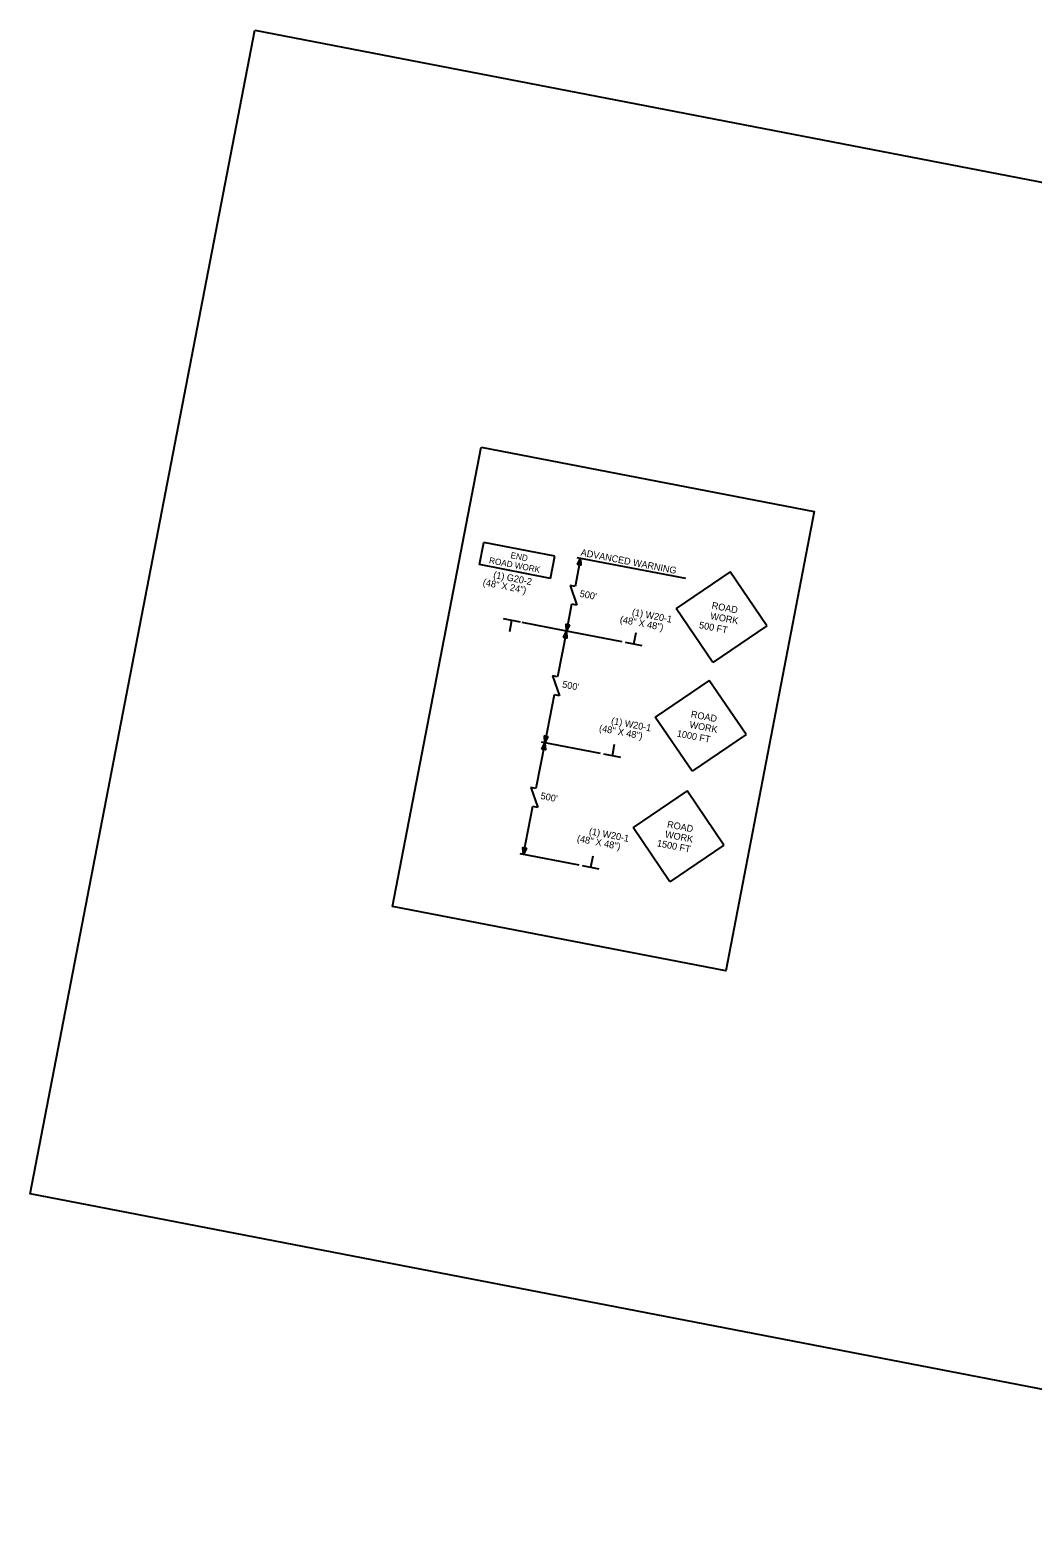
# Model space of a CAD drawing. Extents: x 609776 to 611540, y 418046 to 419372.
# Drawn here: x 609776 to 610658, y 418046 to 419372 of the extents above; entities that cross this region are included whole.
import ezdxf

# ---------------------------------------------------------------- set-up
doc = ezdxf.new("R2010")
doc.units = 0
for name, color, linetype in [('G-Border-Sheet', 7, 'Continuous'), ('R_Draft', 7, 'Continuous'), ('Stage 1B_Sign', 7, 'Continuous')]:
    doc.layers.add(name, color=color, linetype=linetype)

msp = doc.modelspace()

# ---------------------------------------------------------------- linework, layer by layer
at = {"layer": 'G-Border-Sheet'}
msp.add_lwpolyline([(609973.3, 419372.2), (611539.8, 419069.8), (611342.2, 418046.4), (609775.8, 418348.8)], close=True, dxfattribs=at)
at = {"layer": 'R_Draft'}
for p, q in [((610259.9, 418907.8), (610255.1, 418883.1)), ((610352.6, 418889.9), (610257, 418908.3)), ((610255.1, 418883.1), (610250.7, 418884)), ((610250.7, 418884), (610256.8, 418866.5)), ((610252.1, 418867.4), (610247.5, 418843.7)), ((610256.8, 418866.5), (610252.3, 418867.3)), ((610244.6, 418844.2), (610208.5, 418851.2)), ((610247.6, 418843.7), (610239.8, 418803.4)), ((610296.5, 418834.2), (610244.6, 418844.2)), ((610239.8, 418803.4), (610235.3, 418804.3)), ((610235.3, 418804.3), (610241.4, 418786.8)), ((610236.7, 418787.7), (610228.5, 418745.5)), ((610241.4, 418786.8), (610236.9, 418787.7)), ((610228.5, 418745.5), (610220.7, 418705.3)), ((610277.6, 418736), (610225.7, 418746)), ((610220.7, 418705.3), (610216.2, 418706.2)), ((610216.2, 418706.2), (610222.3, 418688.7)), ((610217.6, 418689.6), (610209.5, 418647.4)), ((610222.3, 418688.7), (610217.9, 418689.5)), ((610258.6, 418637.8), (610206.7, 418647.9))]:
    msp.add_line(p, q, dxfattribs=at)
for points in [[(610172.5, 419005.4), (610465.5, 418948.9), (610387.6, 418545), (610094.5, 418601.6)], [(610257.3, 418902.2), (610259.9, 418907.8), (610260.3, 418901.6)], [(610250.2, 418849.3), (610247.6, 418843.7), (610247.2, 418849.8)], [(610245, 418838.1), (610247.6, 418843.7), (610247.9, 418837.5)], [(610226, 418739.9), (610228.6, 418745.5), (610229, 418739.3)], [(610231.2, 418751.1), (610228.6, 418745.5), (610228.3, 418751.7)], [(610212.3, 418652.9), (610209.7, 418647.3), (610209.3, 418653.5)]]:
    msp.add_lwpolyline(points, close=True, dxfattribs=at)
at = {"layer": 'Stage 1B_Sign'}
for p, q in [((610171, 418902.2), (610174.8, 418921.8)), ((610237.2, 418909.7), (610174.8, 418921.8)), ((610233.4, 418890.1), (610171, 418902.2)), ((610233.4, 418890.1), (610237.2, 418909.7)), ((610391.5, 418895.9), (610344, 418863.7)), ((610423.9, 418848.4), (610391.5, 418895.9)), ((610376.3, 418816.1), (610344, 418863.7)), ((610192, 418854.8), (610206.7, 418852)), ((610199.3, 418853.2), (610197.3, 418843.2)), ((610423.9, 418848.4), (610376.3, 418816.1)), ((610314.2, 418830.8), (610299.5, 418833.6)), ((610306.9, 418832.4), (610308.9, 418842.5)), ((610373.2, 418800.3), (610325.7, 418768.1)), ((610405.6, 418752.8), (610373.2, 418800.3)), ((610358, 418720.5), (610325.7, 418768.1)), ((610288, 418734.2), (610289.9, 418744.3)), ((610405.6, 418752.8), (610358, 418720.5)), ((610295.3, 418732.6), (610280.5, 418735.5)), ((610353.8, 418703.2), (610306.2, 418671)), ((610386.1, 418655.6), (610353.8, 418703.2)), ((610338.4, 418623.4), (610306.2, 418671)), ((610386.1, 418655.6), (610338.4, 418623.4)), ((610276.3, 418634.4), (610261.6, 418637.3)), ((610269, 418636.1), (610271, 418646.1))]:
    msp.add_line(p, q, dxfattribs=at)

# ---------------------------------------------------------------- texts
at = {"layer": 'R_Draft'}
for s, p in [('ADVANCED WARNING', (610259.7, 418910.2)), ('(48" X 24")', (610173.6, 418884)), ('(1) G20-2', (610182.8, 418890.6)), ("500'", (610258.8, 418874)), ('(1) W20-1', (610304.8, 418857.8)), ('(48" X 48")', (610294.2, 418851.4)), ("500'", (610243.4, 418794.3)), ('(1) W20-1', (610286.5, 418762.2)), ('(48" X 48")', (610275.9, 418755.8)), ("500'", (610224.4, 418696.2)), ('(48" X 48")', (610256.4, 418658.7)), ('(1) W20-1', (610267, 418665.1))]:
    msp.add_text(s, height=6, rotation=349.0745, dxfattribs=at).set_placement(p)
at = {"layer": 'Stage 1B_Sign'}
for s, height, rotation, p in [('END', 5.42, 349.0745, (610198, 418908)), ('ROAD WORK', 5.42, 349.0745, (610179.1, 418903.5)), ('WORK', 5.99, 349.1748, (610373.7, 418854.4)), ('ROAD', 5.99, 349.175, (610374.9, 418863.6)), (' 500 FT', 5.99, 349.174, (610361.6, 418846.8)), ('ROAD', 5.99, 349.175, (610356.6, 418768)), (' 1000 FT', 5.99, 349.174, (610342.1, 418751.5)), ('WORK', 5.99, 349.1748, (610355.4, 418758.8)), ('ROAD', 5.99, 349.075, (610335.7, 418671.2)), ('WORK', 5.99, 349.0745, (610333.9, 418662.4)), ('1500 FT', 5.99, 349.0751, (610326.8, 418654.6))]:
    msp.add_text(s, height=height, rotation=rotation, dxfattribs=at).set_placement(p)

doc.saveas('drawing.dxf')
